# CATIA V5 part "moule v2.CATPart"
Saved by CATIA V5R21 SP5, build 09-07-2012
Part number: moule v2
Bounding box of the stored display mesh (mm): x -106.75 to 106.75, y -29.25 to 29.25, z -27.5 to 27.5
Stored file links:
  \\salsa.univ-amu.fr\dfs\myhome_etud\DOSSIERS_WINDOWS\Documents\stage s4\CAO\moule v2.CATPart
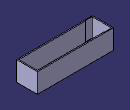
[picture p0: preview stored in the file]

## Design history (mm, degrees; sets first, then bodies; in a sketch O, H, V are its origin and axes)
Body1 (main body)
  Sketch1 on xy-plane, origin (0, 0, 0), H (1, 0, 0), V (0, 1, 0)
    line L1 (-106.75, 29.25) -> (106.75, 29.25)
    line L2 (106.75, 29.25) -> (106.75, -29.25)
    line L3 (106.75, -29.25) -> (-106.75, -29.25)
    line L4 (-106.75, -29.25) -> (-106.75, 29.25)
    distance L4 L2 = 213.5
    length L2 = 58.5
    horizontal: L1 H, L3 H
    vertical: L2 V, L4 V
    symmetry: L2 L4 V, L3 L1 H
  Pad1: profile Sketch1, direction (0, 0, 1), length 27.5, mirrored extent
  Sketch2 on end face of Pad1, origin (0, 0, 27.5), H (1, 0, 0), V (0, 1, 0)
    line L1 (103.75, -26.25) -> (-103.75, -26.25)
    line L2 (-103.75, -26.25) -> (-103.75, 26.25)
    line L3 (-103.75, 26.25) -> (103.75, 26.25)
    line L4 (103.75, 26.25) -> (103.75, -26.25)
    reference projected line E1 (106.75, -29.25) -> (106.75, 29.25) from edge [face of Pad1 from Sketch1.L2 | end face of Pad1]
    reference projected line E2 (106.75, 29.25) -> (-106.75, 29.25) from edge [face of Pad1 from Sketch1.L1 | end face of Pad1]
    distance L4 E1 = 3
    distance L3 E2 = 3
    horizontal: L1 H, L3 H
    vertical: L2 V, L4 V
    symmetry: L4 L2 V, L1 L3 H
  Pocket1: profile Sketch2, direction (0, 0, -1), length 52
  Sketch3 on end face of Pad1, origin (0, 0, 27.5), H (1, 0, 0), V (0, 1, 0)
    line L1 (-103.75, 27.5) -> (-83.75, 27.5)
    line L2 (-83.75, 27.5) -> (-83.75, -27.5)
    line L3 (-83.75, -27.5) -> (-103.75, -27.5)
    line L4 (-103.75, -27.5) -> (-103.75, 27.5)
    reference projected line E1 (-106.75, 29.25) -> (-106.75, -29.25) from edge [face of Pad1 from Sketch1.L4 | end face of Pad1]
    distance L4 E1 = 3
    distance L3 L1 = 55
    length L1 = 20
    horizontal: L1 H, L3 H
    vertical: L2 V, L4 V
    symmetry: L1 L3 H
  Pocket2: profile Sketch3, direction (0, 0, -1), length 52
